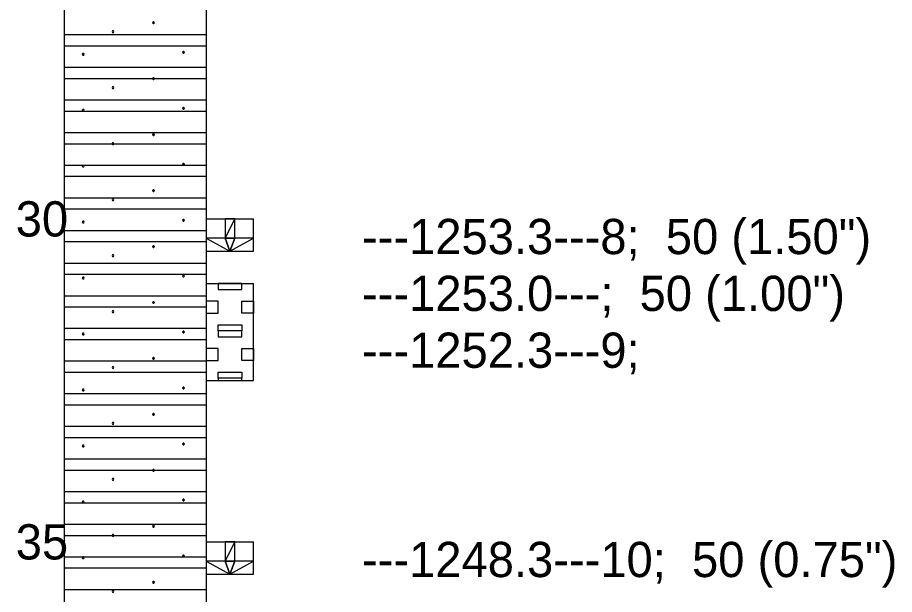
# Model space of a CAD drawing. Extents: x 2150161.5 to 2150203.1, y 143779.5 to 143868.5.
# Drawn here: x 2150191.796 to 2150194.882, y 143821.22 to 143823.25 of the extents above; entities that cross this region are included whole.
import ezdxf

# ---------------------------------------------------------------- set-up
doc = ezdxf.new("R2010")
doc.units = 0
doc.layers.add('Default', color=7, linetype='Continuous')

msp = doc.modelspace()

# ---------------------------------------------------------------- linework, layer by layer
at = {"layer": 'Default'}
for points in [[(2150191.9604, 143829.3595), (2150191.9604, 143817.2004)], [(2150192.4604, 143829.3595), (2150192.4604, 143817.2004)], [(2150192.2781, 143823.2314), (2150192.2764, 143823.2342), (2150192.2731, 143823.2342), (2150192.2715, 143823.2314), (2150192.2731, 143823.2286), (2150192.2764, 143823.2286), (2150192.2781, 143823.2314)], [(2150191.9604, 143823.1898), (2150192.4604, 143823.1898)], [(2150192.1355, 143823.1995), (2150192.1338, 143823.2024), (2150192.1306, 143823.2024), (2150192.1289, 143823.1996), (2150192.1306, 143823.1967), (2150192.1338, 143823.1967), (2150192.1355, 143823.1995)], [(2150191.9604, 143823.1504), (2150192.4604, 143823.1504)], [(2150192.0308, 143823.1206), (2150192.0292, 143823.1234), (2150192.0259, 143823.1234), (2150192.0243, 143823.1206), (2150192.0259, 143823.1177), (2150192.0292, 143823.1177), (2150192.0308, 143823.1206)], [(2150192.3836, 143823.1271), (2150192.3819, 143823.13), (2150192.3787, 143823.13), (2150192.377, 143823.1271), (2150192.3787, 143823.1243), (2150192.3819, 143823.1243), (2150192.3836, 143823.1271)], [(2150191.9604, 143823.0749), (2150192.4604, 143823.0749)], [(2150191.9604, 143823.0356), (2150192.4604, 143823.0356)], [(2150192.2781, 143823.0346), (2150192.2764, 143823.0374), (2150192.2731, 143823.0374), (2150192.2715, 143823.0346), (2150192.2731, 143823.0317), (2150192.2764, 143823.0317), (2150192.2781, 143823.0346)], [(2150192.1355, 143823.0027), (2150192.1338, 143823.0056), (2150192.1306, 143823.0056), (2150192.1289, 143823.0027), (2150192.1306, 143822.9999), (2150192.1338, 143822.9999), (2150192.1355, 143823.0027)], [(2150191.9604, 143822.9601), (2150192.4604, 143822.9601)], [(2150192.3836, 143822.9302), (2150192.3819, 143822.9331), (2150192.3787, 143822.9331), (2150192.377, 143822.9302), (2150192.3787, 143822.9274), (2150192.3819, 143822.9274), (2150192.3836, 143822.9302)], [(2150191.9604, 143822.9207), (2150192.4604, 143822.9207)], [(2150192.0308, 143822.9237), (2150192.0292, 143822.9266), (2150192.0259, 143822.9266), (2150192.0243, 143822.9237), (2150192.0259, 143822.9209), (2150192.0292, 143822.9209), (2150192.0308, 143822.9237)], [(2150191.9604, 143822.8453), (2150192.4604, 143822.8453)], [(2150192.2781, 143822.8377), (2150192.2764, 143822.8405), (2150192.2731, 143822.8405), (2150192.2715, 143822.8377), (2150192.2731, 143822.8349), (2150192.2764, 143822.8349), (2150192.2781, 143822.8377)], [(2150192.1355, 143822.8058), (2150192.1338, 143822.8087), (2150192.1306, 143822.8087), (2150192.1289, 143822.8059), (2150192.1306, 143822.803), (2150192.1338, 143822.803), (2150192.1355, 143822.8058)], [(2150191.9604, 143822.8059), (2150192.4604, 143822.8059)], [(2150191.9604, 143822.7304), (2150192.4604, 143822.7304)], [(2150192.0308, 143822.7269), (2150192.0292, 143822.7297), (2150192.0259, 143822.7297), (2150192.0243, 143822.7269), (2150192.0259, 143822.724), (2150192.0292, 143822.724), (2150192.0308, 143822.7269)], [(2150192.3836, 143822.7334), (2150192.3819, 143822.7363), (2150192.3787, 143822.7363), (2150192.377, 143822.7334), (2150192.3787, 143822.7306), (2150192.3819, 143822.7306), (2150192.3836, 143822.7334)], [(2150191.9604, 143822.6911), (2150192.4604, 143822.6911)], [(2150192.2781, 143822.6409), (2150192.2764, 143822.6437), (2150192.2731, 143822.6437), (2150192.2715, 143822.6409), (2150192.2731, 143822.638), (2150192.2764, 143822.638), (2150192.2781, 143822.6409)], [(2150191.9604, 143822.6156), (2150192.4604, 143822.6156)], [(2150192.1355, 143822.609), (2150192.1338, 143822.6119), (2150192.1306, 143822.6119), (2150192.1289, 143822.609), (2150192.1306, 143822.6062), (2150192.1338, 143822.6062), (2150192.1355, 143822.609)], [(2150191.9604, 143822.5762), (2150192.4604, 143822.5762)], [(2150192.0308, 143822.53), (2150192.0292, 143822.5329), (2150192.0259, 143822.5329), (2150192.0243, 143822.53), (2150192.0259, 143822.5272), (2150192.0292, 143822.5272), (2150192.0308, 143822.53)], [(2150192.3836, 143822.5365), (2150192.3819, 143822.5394), (2150192.3787, 143822.5394), (2150192.377, 143822.5365), (2150192.3787, 143822.5337), (2150192.3819, 143822.5337), (2150192.3836, 143822.5365)], [(2150192.4604, 143822.5413), (2150192.6271, 143822.5413)], [(2150192.6271, 143822.4277), (2150192.6271, 143822.5413)], [(2150191.9604, 143822.5008), (2150192.4604, 143822.5008)], [(2150191.9604, 143822.4614), (2150192.4604, 143822.4614)], [(2150192.2781, 143822.444), (2150192.2764, 143822.4468), (2150192.2731, 143822.4468), (2150192.2715, 143822.444), (2150192.2731, 143822.4412), (2150192.2764, 143822.4412), (2150192.2781, 143822.444)], [(2150192.1355, 143822.4121), (2150192.1338, 143822.415), (2150192.1306, 143822.415), (2150192.1289, 143822.4122), (2150192.1306, 143822.4093), (2150192.1338, 143822.4093), (2150192.1355, 143822.4121)], [(2150192.4604, 143822.4277), (2150192.6271, 143822.4277)], [(2150191.9604, 143822.3859), (2150192.4604, 143822.3859)], [(2150191.9604, 143822.3466), (2150192.4604, 143822.3466)], [(2150192.0308, 143822.3332), (2150192.0292, 143822.336), (2150192.0259, 143822.336), (2150192.0243, 143822.3332), (2150192.0259, 143822.3303), (2150192.0292, 143822.3303), (2150192.0308, 143822.3332)], [(2150192.3836, 143822.3397), (2150192.3819, 143822.3426), (2150192.3787, 143822.3426), (2150192.377, 143822.3397), (2150192.3787, 143822.3369), (2150192.3819, 143822.3369), (2150192.3836, 143822.3397)], [(2150192.4604, 143822.3141), (2150192.6271, 143822.3141)], [(2150192.6271, 143821.9732), (2150192.6271, 143822.3141)], [(2150191.9604, 143822.2711), (2150192.4604, 143822.2711)], [(2150191.9604, 143822.2317), (2150192.4604, 143822.2317)], [(2150192.2781, 143822.2472), (2150192.2764, 143822.25), (2150192.2731, 143822.25), (2150192.2715, 143822.2472), (2150192.2731, 143822.2443), (2150192.2764, 143822.2443), (2150192.2781, 143822.2472)], [(2150192.1355, 143822.2153), (2150192.1338, 143822.2182), (2150192.1306, 143822.2182), (2150192.1289, 143822.2153), (2150192.1306, 143822.2125), (2150192.1338, 143822.2125), (2150192.1355, 143822.2153)], [(2150191.9604, 143822.1563), (2150192.4604, 143822.1563)], [(2150192.0308, 143822.1363), (2150192.0292, 143822.1392), (2150192.0259, 143822.1392), (2150192.0243, 143822.1363), (2150192.0259, 143822.1335), (2150192.0292, 143822.1335), (2150192.0308, 143822.1363)], [(2150192.3836, 143822.1428), (2150192.3819, 143822.1457), (2150192.3787, 143822.1457), (2150192.377, 143822.1428), (2150192.3787, 143822.14), (2150192.3819, 143822.14), (2150192.3836, 143822.1428)], [(2150191.9604, 143822.1169), (2150192.4604, 143822.1169)], [(2150191.9604, 143822.0415), (2150192.4604, 143822.0415)], [(2150192.2781, 143822.0503), (2150192.2764, 143822.0531), (2150192.2731, 143822.0531), (2150192.2715, 143822.0503), (2150192.2731, 143822.0475), (2150192.2764, 143822.0475), (2150192.2781, 143822.0503)], [(2150192.1355, 143822.0184), (2150192.1338, 143822.0213), (2150192.1306, 143822.0213), (2150192.1289, 143822.0185), (2150192.1306, 143822.0156), (2150192.1338, 143822.0156), (2150192.1355, 143822.0184)], [(2150191.9604, 143822.0021), (2150192.4604, 143822.0021)], [(2150192.4604, 143821.9732), (2150192.6271, 143821.9732)], [(2150192.0308, 143821.9395), (2150192.0292, 143821.9423), (2150192.0259, 143821.9423), (2150192.0243, 143821.9395), (2150192.0259, 143821.9366), (2150192.0292, 143821.9366), (2150192.0308, 143821.9395)], [(2150192.3836, 143821.946), (2150192.3819, 143821.9489), (2150192.3787, 143821.9489), (2150192.377, 143821.946), (2150192.3787, 143821.9432), (2150192.3819, 143821.9432), (2150192.3836, 143821.946)], [(2150191.9604, 143821.9266), (2150192.4604, 143821.9266)], [(2150191.9604, 143821.8873), (2150192.4604, 143821.8873)], [(2150192.2781, 143821.8535), (2150192.2764, 143821.8563), (2150192.2731, 143821.8563), (2150192.2715, 143821.8535), (2150192.2731, 143821.8506), (2150192.2764, 143821.8506), (2150192.2781, 143821.8535)], [(2150192.1355, 143821.8216), (2150192.1338, 143821.8245), (2150192.1306, 143821.8245), (2150192.1289, 143821.8216), (2150192.1306, 143821.8188), (2150192.1338, 143821.8188), (2150192.1355, 143821.8216)], [(2150191.9604, 143821.8118), (2150192.4604, 143821.8118)], [(2150191.9604, 143821.7724), (2150192.4604, 143821.7724)], [(2150192.0308, 143821.7426), (2150192.0292, 143821.7455), (2150192.0259, 143821.7455), (2150192.0243, 143821.7426), (2150192.0259, 143821.7398), (2150192.0292, 143821.7398), (2150192.0308, 143821.7426)], [(2150192.3836, 143821.7491), (2150192.3819, 143821.752), (2150192.3787, 143821.752), (2150192.377, 143821.7491), (2150192.3787, 143821.7463), (2150192.3819, 143821.7463), (2150192.3836, 143821.7491)], [(2150191.9604, 143821.697), (2150192.4604, 143821.697)], [(2150191.9604, 143821.6576), (2150192.4604, 143821.6576)], [(2150192.2781, 143821.6566), (2150192.2764, 143821.6594), (2150192.2731, 143821.6594), (2150192.2715, 143821.6566), (2150192.2731, 143821.6538), (2150192.2764, 143821.6538), (2150192.2781, 143821.6566)], [(2150192.1355, 143821.6247), (2150192.1338, 143821.6276), (2150192.1306, 143821.6276), (2150192.1289, 143821.6248), (2150192.1306, 143821.6219), (2150192.1338, 143821.6219), (2150192.1355, 143821.6247)], [(2150191.9604, 143821.5821), (2150192.4604, 143821.5821)], [(2150191.9604, 143821.5428), (2150192.4604, 143821.5428)], [(2150192.0308, 143821.5458), (2150192.0292, 143821.5486), (2150192.0259, 143821.5486), (2150192.0243, 143821.5458), (2150192.0259, 143821.5429), (2150192.0292, 143821.5429), (2150192.0308, 143821.5458)], [(2150192.3836, 143821.5523), (2150192.3819, 143821.5552), (2150192.3787, 143821.5552), (2150192.377, 143821.5523), (2150192.3787, 143821.5495), (2150192.3819, 143821.5495), (2150192.3836, 143821.5523)], [(2150191.9604, 143821.4673), (2150192.4604, 143821.4673)], [(2150192.2781, 143821.4598), (2150192.2764, 143821.4626), (2150192.2731, 143821.4626), (2150192.2715, 143821.4598), (2150192.2731, 143821.4569), (2150192.2764, 143821.4569), (2150192.2781, 143821.4598)], [(2150191.9604, 143821.4279), (2150192.4604, 143821.4279)], [(2150192.1355, 143821.4279), (2150192.1338, 143821.4308), (2150192.1306, 143821.4308), (2150192.1289, 143821.4279), (2150192.1306, 143821.4251), (2150192.1338, 143821.4251), (2150192.1355, 143821.4279)], [(2150192.4604, 143821.405), (2150192.6271, 143821.405)], [(2150192.6271, 143821.2913), (2150192.6271, 143821.405)], [(2150192.3836, 143821.3554), (2150192.3819, 143821.3583), (2150192.3787, 143821.3583), (2150192.377, 143821.3554), (2150192.3787, 143821.3526), (2150192.3819, 143821.3526), (2150192.3836, 143821.3554)], [(2150191.9604, 143821.3525), (2150192.4604, 143821.3525)], [(2150192.0308, 143821.3489), (2150192.0292, 143821.3518), (2150192.0259, 143821.3518), (2150192.0243, 143821.3489), (2150192.0259, 143821.3461), (2150192.0292, 143821.3461), (2150192.0308, 143821.3489)], [(2150191.9604, 143821.3131), (2150192.4604, 143821.3131)], [(2150192.2781, 143821.2629), (2150192.2764, 143821.2657), (2150192.2731, 143821.2657), (2150192.2715, 143821.2629), (2150192.2731, 143821.2601), (2150192.2764, 143821.2601), (2150192.2781, 143821.2629)], [(2150192.4604, 143821.2913), (2150192.6271, 143821.2913)], [(2150191.9604, 143821.2377), (2150192.4604, 143821.2377)], [(2150192.1355, 143821.231), (2150192.1338, 143821.2339), (2150192.1306, 143821.2339), (2150192.1289, 143821.2311), (2150192.1306, 143821.2282), (2150192.1338, 143821.2282), (2150192.1355, 143821.231)]]:
    msp.add_lwpolyline(points, dxfattribs=at)
for points in [[(2150192.5271, 143822.4732), (2150192.5604, 143822.4732), (2150192.5604, 143822.5413), (2150192.5271, 143822.4732)], [(2150192.5271, 143822.4732), (2150192.5604, 143822.5413), (2150192.5271, 143822.5413), (2150192.5271, 143822.4732)], [(2150192.5271, 143822.4732), (2150192.4604, 143822.4732), (2150192.5437, 143822.4277), (2150192.5271, 143822.4732)], [(2150192.5271, 143822.4732), (2150192.5437, 143822.4277), (2150192.5604, 143822.4732), (2150192.5271, 143822.4732)], [(2150192.5437, 143822.4277), (2150192.6271, 143822.4732), (2150192.5604, 143822.4732), (2150192.5437, 143822.4277)], [(2150192.5021, 143822.3141), (2150192.5021, 143822.2932), (2150192.5854, 143822.2932), (2150192.5854, 143822.3141)], [(2150192.4604, 143822.2099), (2150192.5021, 143822.2099), (2150192.5021, 143822.2516), (2150192.4604, 143822.2516)], [(2150192.6271, 143822.2099), (2150192.5854, 143822.2099), (2150192.5854, 143822.2516), (2150192.6271, 143822.2516)], [(2150192.5021, 143822.1474), (2150192.5021, 143822.1682), (2150192.5854, 143822.1682), (2150192.5854, 143822.1474)], [(2150192.5021, 143822.1474), (2150192.5021, 143822.1266), (2150192.5854, 143822.1266), (2150192.5854, 143822.1474)], [(2150192.4604, 143822.0432), (2150192.5021, 143822.0432), (2150192.5021, 143822.0849), (2150192.4604, 143822.0849)], [(2150192.6271, 143822.0432), (2150192.5854, 143822.0432), (2150192.5854, 143822.0849), (2150192.6271, 143822.0849)], [(2150192.5021, 143821.9807), (2150192.5021, 143822.0016), (2150192.5854, 143822.0016), (2150192.5854, 143821.9807)], [(2150192.5854, 143821.9807), (2150192.5021, 143821.9807), (2150192.5021, 143821.9732), (2150192.5854, 143821.9732)], [(2150192.5271, 143821.3368), (2150192.5604, 143821.3368), (2150192.5604, 143821.405), (2150192.5271, 143821.3368)], [(2150192.5271, 143821.3368), (2150192.5604, 143821.405), (2150192.5271, 143821.405), (2150192.5271, 143821.3368)], [(2150192.5271, 143821.3368), (2150192.4604, 143821.3368), (2150192.5437, 143821.2913), (2150192.5271, 143821.3368)], [(2150192.5271, 143821.3368), (2150192.5437, 143821.2913), (2150192.5604, 143821.3368), (2150192.5271, 143821.3368)], [(2150192.5437, 143821.2913), (2150192.6271, 143821.3368), (2150192.5604, 143821.3368), (2150192.5437, 143821.2913)]]:
    msp.add_lwpolyline(points, close=True, dxfattribs=at)

# ---------------------------------------------------------------- texts
for s, p in [('30', (2150191.79, 143822.4793)), ('---1253.3---8;  50 (1.50")', (2150193.0084, 143822.4173)), ('---1253.0---;  50 (1.00")', (2150193.0084, 143822.2173)), ('---1252.3---9;', (2150193.0084, 143822.0173)), ('35', (2150191.79, 143821.343)), ('---1248.3---10;  50 (0.75")', (2150193.0084, 143821.281))]:
    msp.add_text(s, height=0.124, dxfattribs=at).set_placement(p)

doc.saveas('drawing.dxf')
